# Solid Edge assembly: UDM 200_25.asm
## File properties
Title: Zylinder
Author: ahadarics
Template: iso assembly.asm
Last saved by: ahadarics
Revision: 21
Application: Solid Edge
Username: ahadarics
Dokumentum tartalom típus: 1
Document Number: UDM 200/25
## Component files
Profilrohr 200_25.par
Mutter.par
Kolbenstange 200_25.par
Kit_1.par
Zugstange 200_25.par
Kit_2.par
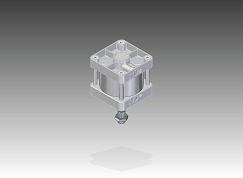
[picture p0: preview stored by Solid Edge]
